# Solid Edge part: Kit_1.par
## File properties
Dokumentum tartalom típus: 0
Last saved by: bmolnar
Revision: 79
Sűrűség: 0,000 kg/m^3
Pontosság: 0,990
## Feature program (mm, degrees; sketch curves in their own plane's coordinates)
base feature "unnamed BaseFeature 1"
sketch for "unnamed Cutout 1" plane through (-0.0012, 0, 85.35) normal (0, 0, -1) x-axis (-1, 0, 0)
  circle centre (-0.0012, 0) radius 8
extrude "unnamed Cutout 1" cut through along -normal
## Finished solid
Body 1: solid body, 42 faces, 59 edges, 25 vertices, 1 internal void.
  Faces by surface: cylinder 15, cone 13, plane 11, torus 3
  Edges by curve: circle 45, line 14
Bounding box of the edges (mm; curved faces can reach further): 68.000 x 67.800 x 14.650, from (-34, -32.35, 85.35) to (34, 35.45, 100).
Cylindrical faces by radius (mm): R1.5 x2, R3 x4, R8 x1, R8.27 x1, R8.85 x1, R9 x1, R10.25 x1, R19.25 x1, R29.65 x1, R32.35 x1, R34 x1
Conical faces (half-angle, radius in mm at the cone's reference point): 7 deg R9.5925 x1, 14 deg R8.135 x1, 14 deg R8.4811 x1, 17 deg R8.135 x1, 23 deg R8.829 x1, 42.5 deg R8.1233 x1, 45 deg R9.1 x2, 45 deg R18.75 x1, 84 deg R76.3675 x2, 85 deg R9.9463 x1, 87 deg R8.1765 x1
Toroidal faces (ring radius, tube radius in mm): R8.8057 r0.2025 x1, R9.2522 r0.2925 x1, R20.05 r0.8 x1
Planar faces by outward normal: +z 7, -z 2, oblique 2
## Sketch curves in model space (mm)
circle centre (0, 0, 85.35) radius 8
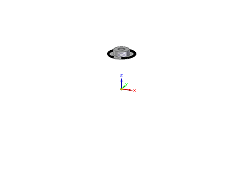
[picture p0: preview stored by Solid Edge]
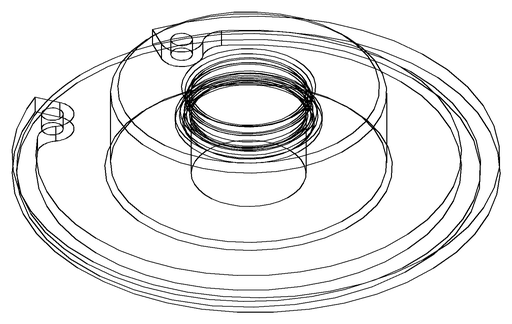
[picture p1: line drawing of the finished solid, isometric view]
